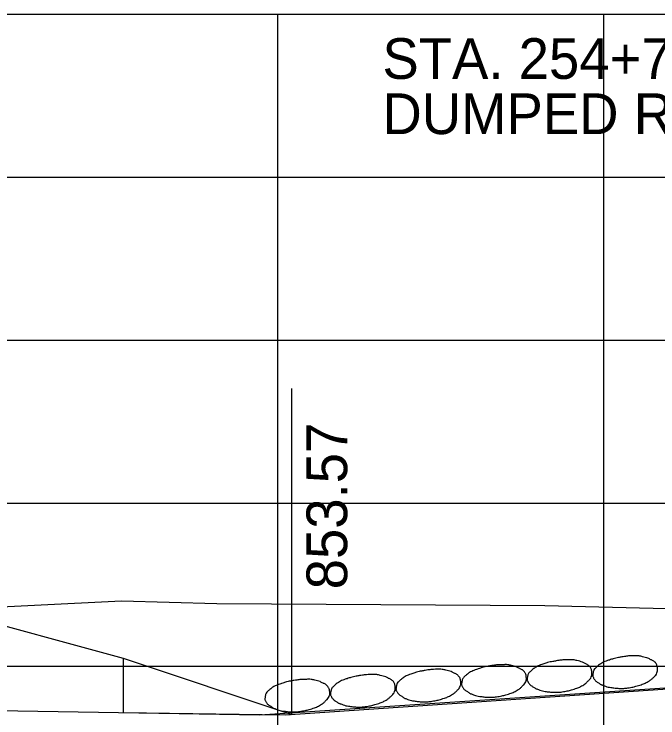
# Model space of a CAD drawing. Extents: x 1486524 to 1499135, y 326561 to 337924.
# Drawn here: x 1489014.79 to 1489034.55, y 328437.6 to 328459.19 of the extents above; entities that cross this region are included whole.
import ezdxf

# ---------------------------------------------------------------- set-up
doc = ezdxf.new("R2010")
doc.units = 0
for name, color, linetype in [('E_Ownership Information', 7, 'Continuous'), ('E_Proposed ROW Fig Annot', 7, 'Continuous'), ('E_Station Offset', 7, 'Continuous'), ('R_Xsect Elev', 7, 'Continuous'), ('T_Notes', 7, 'Continuous')]:
    doc.layers.add(name, color=color, linetype=linetype)

msp = doc.modelspace()

# ---------------------------------------------------------------- linework, layer by layer
at = {"layer": 'E_Ownership Information'}
for p, q in [((1488842.885, 328459.191), (1489122.885, 328459.191)), ((1489022.885, 328429.191), (1489022.885, 328459.191)), ((1489032.885, 328429.191), (1489032.885, 328459.191)), ((1488842.885, 328454.191), (1489122.885, 328454.191)), ((1488842.885, 328449.191), (1489122.885, 328449.191)), ((1488842.885, 328444.191), (1489122.885, 328444.191)), ((1488842.885, 328439.191), (1489122.885, 328439.191))]:
    msp.add_line(p, q, dxfattribs=at)
at = {"layer": 'E_Proposed ROW Fig Annot'}
for p, q in [((1489018.133, 328439.435), (1489018.133, 328437.765)), ((1488941.814, 328438.994), (1489022.333, 328437.698))]:
    msp.add_line(p, q, dxfattribs=at)
for points in [[(1489030.589, 328438.986), (1489030.572, 328438.968), (1489030.559, 328438.942), (1489030.549, 328438.896), (1489030.545, 328438.876), (1489030.537, 328438.828), (1489030.532, 328438.801), (1489030.531, 328438.759), (1489030.541, 328438.744), (1489030.561, 328438.702), (1489030.574, 328438.678), (1489030.607, 328438.634), (1489030.624, 328438.615), (1489030.675, 328438.579), (1489030.706, 328438.562), (1489030.755, 328438.529), (1489030.773, 328438.512), (1489030.809, 328438.492), (1489030.828, 328438.493), (1489030.88, 328438.474), (1489030.913, 328438.454), (1489031.011, 328438.426), (1489031.072, 328438.416), (1489031.226, 328438.396), (1489031.317, 328438.386), (1489031.5, 328438.387), (1489031.592, 328438.398), (1489031.781, 328438.431), (1489031.876, 328438.456), (1489032.071, 328438.516), (1489032.164, 328438.556), (1489032.314, 328438.645), (1489032.361, 328438.691), (1489032.449, 328438.779), (1489032.485, 328438.817), (1489032.519, 328438.905), (1489032.52, 328438.939), (1489032.519, 328439.004), (1489032.517, 328439.034), (1489032.503, 328439.096), (1489032.491, 328439.127), (1489032.459, 328439.173), (1489032.446, 328439.187), (1489032.412, 328439.216), (1489032.394, 328439.232), (1489032.347, 328439.255), (1489032.321, 328439.265), (1489032.266, 328439.292), (1489032.239, 328439.315), (1489032.139, 328439.34), (1489032.071, 328439.357), (1489031.942, 328439.39), (1489031.878, 328439.387), (1489031.729, 328439.385), (1489031.642, 328439.384), (1489031.496, 328439.364), (1489031.434, 328439.353), (1489031.31, 328439.331), (1489031.246, 328439.323), (1489031.15, 328439.295), (1489031.118, 328439.282), (1489031.04, 328439.256), (1489030.995, 328439.242), (1489030.898, 328439.21), (1489030.849, 328439.185), (1489030.771, 328439.141), (1489030.743, 328439.123), (1489030.681, 328439.073), (1489030.649, 328439.043), (1489030.6, 328438.998), (1489030.584, 328438.985), (1489030.573, 328438.966)], [(1489032.602, 328439.106), (1489032.585, 328439.088), (1489032.573, 328439.062), (1489032.562, 328439.016), (1489032.558, 328438.996), (1489032.55, 328438.948), (1489032.545, 328438.922), (1489032.545, 328438.879), (1489032.554, 328438.864), (1489032.574, 328438.822), (1489032.587, 328438.798), (1489032.621, 328438.754), (1489032.638, 328438.735), (1489032.688, 328438.699), (1489032.719, 328438.682), (1489032.769, 328438.649), (1489032.786, 328438.632), (1489032.822, 328438.612), (1489032.841, 328438.613), (1489032.893, 328438.594), (1489032.927, 328438.574), (1489033.024, 328438.546), (1489033.086, 328438.536), (1489033.239, 328438.516), (1489033.33, 328438.507), (1489033.514, 328438.507), (1489033.606, 328438.519), (1489033.794, 328438.551), (1489033.889, 328438.576), (1489034.084, 328438.636), (1489034.177, 328438.676), (1489034.327, 328438.765), (1489034.374, 328438.811), (1489034.462, 328438.9), (1489034.498, 328438.937), (1489034.533, 328439.025), (1489034.533, 328439.059), (1489034.532, 328439.124), (1489034.531, 328439.155), (1489034.516, 328439.216), (1489034.504, 328439.247), (1489034.473, 328439.294), (1489034.459, 328439.307), (1489034.425, 328439.336), (1489034.407, 328439.352), (1489034.36, 328439.375), (1489034.334, 328439.385), (1489034.279, 328439.412), (1489034.253, 328439.435), (1489034.152, 328439.46), (1489034.084, 328439.478), (1489033.955, 328439.51), (1489033.891, 328439.507), (1489033.742, 328439.505), (1489033.655, 328439.505), (1489033.509, 328439.484), (1489033.448, 328439.473), (1489033.323, 328439.451), (1489033.259, 328439.443), (1489033.163, 328439.415), (1489033.131, 328439.402), (1489033.053, 328439.376), (1489033.008, 328439.362), (1489032.912, 328439.33), (1489032.862, 328439.305), (1489032.784, 328439.262), (1489032.756, 328439.243), (1489032.694, 328439.194), (1489032.662, 328439.163), (1489032.614, 328439.119), (1489032.598, 328439.105), (1489032.586, 328439.086)], [(1489028.578, 328438.835), (1489028.561, 328438.817), (1489028.548, 328438.79), (1489028.538, 328438.744), (1489028.534, 328438.724), (1489028.526, 328438.677), (1489028.52, 328438.65), (1489028.52, 328438.608), (1489028.529, 328438.593), (1489028.55, 328438.551), (1489028.563, 328438.527), (1489028.596, 328438.482), (1489028.613, 328438.463), (1489028.664, 328438.428), (1489028.695, 328438.411), (1489028.744, 328438.378), (1489028.762, 328438.36), (1489028.798, 328438.34), (1489028.816, 328438.341), (1489028.869, 328438.323), (1489028.902, 328438.303), (1489029, 328438.274), (1489029.061, 328438.264), (1489029.215, 328438.244), (1489029.306, 328438.235), (1489029.489, 328438.235), (1489029.581, 328438.247), (1489029.769, 328438.28), (1489029.865, 328438.304), (1489030.059, 328438.365), (1489030.153, 328438.405), (1489030.303, 328438.494), (1489030.35, 328438.539), (1489030.438, 328438.628), (1489030.473, 328438.666), (1489030.508, 328438.753), (1489030.509, 328438.788), (1489030.508, 328438.853), (1489030.506, 328438.883), (1489030.492, 328438.945), (1489030.48, 328438.976), (1489030.448, 328439.022), (1489030.435, 328439.036), (1489030.401, 328439.065), (1489030.382, 328439.08), (1489030.336, 328439.104), (1489030.31, 328439.114), (1489030.255, 328439.14), (1489030.228, 328439.163), (1489030.128, 328439.189), (1489030.06, 328439.206), (1489029.931, 328439.239), (1489029.867, 328439.235), (1489029.718, 328439.234), (1489029.631, 328439.233), (1489029.484, 328439.212), (1489029.423, 328439.201), (1489029.299, 328439.179), (1489029.235, 328439.171), (1489029.139, 328439.144), (1489029.107, 328439.13), (1489029.029, 328439.105), (1489028.984, 328439.091), (1489028.887, 328439.058), (1489028.838, 328439.033), (1489028.76, 328438.99), (1489028.731, 328438.971), (1489028.67, 328438.922), (1489028.638, 328438.892), (1489028.589, 328438.847), (1489028.573, 328438.834), (1489028.561, 328438.815)], [(1489024.555, 328438.534), (1489024.538, 328438.516), (1489024.526, 328438.49), (1489024.515, 328438.443), (1489024.512, 328438.423), (1489024.504, 328438.376), (1489024.498, 328438.349), (1489024.498, 328438.307), (1489024.507, 328438.292), (1489024.528, 328438.25), (1489024.541, 328438.226), (1489024.574, 328438.182), (1489024.591, 328438.162), (1489024.641, 328438.127), (1489024.673, 328438.11), (1489024.722, 328438.077), (1489024.739, 328438.06), (1489024.776, 328438.039), (1489024.794, 328438.04), (1489024.846, 328438.022), (1489024.88, 328438.002), (1489024.977, 328437.974), (1489025.039, 328437.964), (1489025.193, 328437.943), (1489025.283, 328437.934), (1489025.467, 328437.935), (1489025.559, 328437.946), (1489025.747, 328437.979), (1489025.843, 328438.003), (1489026.037, 328438.064), (1489026.13, 328438.104), (1489026.28, 328438.193), (1489026.328, 328438.238), (1489026.416, 328438.327), (1489026.451, 328438.365), (1489026.486, 328438.453), (1489026.486, 328438.487), (1489026.486, 328438.552), (1489026.484, 328438.582), (1489026.469, 328438.644), (1489026.457, 328438.675), (1489026.426, 328438.721), (1489026.413, 328438.735), (1489026.378, 328438.764), (1489026.36, 328438.78), (1489026.314, 328438.803), (1489026.288, 328438.813), (1489026.233, 328438.84), (1489026.206, 328438.862), (1489026.106, 328438.888), (1489026.038, 328438.905), (1489025.909, 328438.938), (1489025.844, 328438.935), (1489025.695, 328438.933), (1489025.609, 328438.932), (1489025.462, 328438.911), (1489025.401, 328438.901), (1489025.276, 328438.878), (1489025.212, 328438.87), (1489025.117, 328438.843), (1489025.084, 328438.83), (1489025.007, 328438.804), (1489024.962, 328438.79), (1489024.865, 328438.757), (1489024.816, 328438.733), (1489024.737, 328438.689), (1489024.709, 328438.67), (1489024.647, 328438.621), (1489024.615, 328438.591), (1489024.567, 328438.546), (1489024.551, 328438.533), (1489024.539, 328438.514)], [(1489026.566, 328438.694), (1489026.549, 328438.676), (1489026.536, 328438.649), (1489026.526, 328438.603), (1489026.522, 328438.583), (1489026.514, 328438.536), (1489026.508, 328438.509), (1489026.508, 328438.467), (1489026.517, 328438.452), (1489026.538, 328438.41), (1489026.551, 328438.386), (1489026.584, 328438.341), (1489026.601, 328438.322), (1489026.652, 328438.287), (1489026.683, 328438.27), (1489026.732, 328438.237), (1489026.75, 328438.22), (1489026.786, 328438.199), (1489026.805, 328438.2), (1489026.857, 328438.182), (1489026.89, 328438.162), (1489026.988, 328438.133), (1489027.049, 328438.123), (1489027.203, 328438.103), (1489027.294, 328438.094), (1489027.477, 328438.094), (1489027.569, 328438.106), (1489027.758, 328438.139), (1489027.853, 328438.163), (1489028.048, 328438.224), (1489028.141, 328438.264), (1489028.291, 328438.353), (1489028.338, 328438.398), (1489028.426, 328438.487), (1489028.462, 328438.525), (1489028.496, 328438.612), (1489028.497, 328438.647), (1489028.496, 328438.712), (1489028.494, 328438.742), (1489028.48, 328438.804), (1489028.468, 328438.835), (1489028.436, 328438.881), (1489028.423, 328438.895), (1489028.389, 328438.924), (1489028.371, 328438.94), (1489028.324, 328438.963), (1489028.298, 328438.973), (1489028.243, 328438.999), (1489028.216, 328439.022), (1489028.116, 328439.048), (1489028.048, 328439.065), (1489027.919, 328439.098), (1489027.855, 328439.094), (1489027.706, 328439.093), (1489027.619, 328439.092), (1489027.473, 328439.071), (1489027.411, 328439.06), (1489027.287, 328439.038), (1489027.223, 328439.03), (1489027.127, 328439.003), (1489027.095, 328438.989), (1489027.017, 328438.964), (1489026.972, 328438.95), (1489026.875, 328438.917), (1489026.826, 328438.893), (1489026.748, 328438.849), (1489026.72, 328438.83), (1489026.658, 328438.781), (1489026.626, 328438.751), (1489026.577, 328438.706), (1489026.561, 328438.693), (1489026.55, 328438.674)], [(1489022.544, 328438.386), (1489022.527, 328438.368), (1489022.514, 328438.342), (1489022.504, 328438.295), (1489022.5, 328438.275), (1489022.492, 328438.228), (1489022.487, 328438.201), (1489022.486, 328438.159), (1489022.496, 328438.144), (1489022.516, 328438.102), (1489022.529, 328438.078), (1489022.562, 328438.034), (1489022.579, 328438.014), (1489022.63, 328437.979), (1489022.661, 328437.962), (1489022.711, 328437.929), (1489022.728, 328437.912), (1489022.764, 328437.891), (1489022.783, 328437.892), (1489022.835, 328437.874), (1489022.868, 328437.854), (1489022.966, 328437.825), (1489023.028, 328437.815), (1489023.181, 328437.795), (1489023.272, 328437.786), (1489023.456, 328437.787), (1489023.548, 328437.798), (1489023.736, 328437.831), (1489023.831, 328437.855), (1489024.026, 328437.916), (1489024.119, 328437.956), (1489024.269, 328438.045), (1489024.316, 328438.09), (1489024.404, 328438.179), (1489024.44, 328438.217), (1489024.475, 328438.304), (1489024.475, 328438.339), (1489024.474, 328438.404), (1489024.472, 328438.434), (1489024.458, 328438.496), (1489024.446, 328438.527), (1489024.414, 328438.573), (1489024.401, 328438.587), (1489024.367, 328438.616), (1489024.349, 328438.632), (1489024.302, 328438.655), (1489024.276, 328438.665), (1489024.221, 328438.692), (1489024.195, 328438.714), (1489024.094, 328438.74), (1489024.026, 328438.757), (1489023.897, 328438.79), (1489023.833, 328438.786), (1489023.684, 328438.785), (1489023.597, 328438.784), (1489023.451, 328438.763), (1489023.39, 328438.753), (1489023.265, 328438.73), (1489023.201, 328438.722), (1489023.105, 328438.695), (1489023.073, 328438.682), (1489022.995, 328438.656), (1489022.95, 328438.642), (1489022.853, 328438.609), (1489022.804, 328438.585), (1489022.726, 328438.541), (1489022.698, 328438.522), (1489022.636, 328438.473), (1489022.604, 328438.443), (1489022.556, 328438.398), (1489022.54, 328438.385), (1489022.528, 328438.366)]]:
    msp.add_open_spline(points, degree=3, dxfattribs=at)
at = {"layer": 'E_Station Offset'}
msp.add_line((1489018.133, 328439.435), (1489023.308, 328437.711), dxfattribs=at)
at = {"layer": 'R_Xsect Elev'}
msp.add_line((1489023.308, 328437.711), (1489023.308, 328447.711), dxfattribs=at)
at = {"layer": 'T_Notes'}
for p, q in [((1489022.333, 328437.698), (1489062.966, 328440.404)), ((1488945.123, 328438.941), (1489022.333, 328437.698))]:
    msp.add_line(p, q, dxfattribs=at)
for points in [[(1488924.201, 328444.819), (1488941.814, 328438.994), (1488945.123, 328438.941), (1488948.403, 328438.888), (1488948.403, 328440.558), (1488953.653, 328441.804), (1488965.953, 328443.793), (1488965.991, 328443.803), (1488969.607, 328443.947), (1488969.653, 328443.949), (1488982.72, 328444.21), (1488982.885, 328444.214), (1488994.732, 328444.128), (1488994.885, 328444.126), (1488994.936, 328444.124), (1488998.989, 328443.962), (1488999.026, 328443.953), (1489012.883, 328440.868), (1489018.133, 328439.435), (1489018.133, 328437.765), (1489023.119, 328437.698), (1489062.966, 328440.404)], [(1489012.538, 328440.92), (1489018.082, 328441.198), (1489021.013, 328441.107), (1489031.072, 328441.046), (1489052.675, 328440.521), (1489056.279, 328440.356)]]:
    msp.add_lwpolyline(points, dxfattribs=at)

# ---------------------------------------------------------------- texts
at = {"layer": 'E_Proposed ROW Fig Annot'}
for s, p in [('STA. 254+73 INSTALL', (1489026.093, 328457.202)), ('DUMPED RIPRAP ON RT. 12 CU.YD.', (1489026.093, 328455.509))]:
    msp.add_text(s, height=1.25, dxfattribs=at).set_placement(p)
at = {"layer": 'T_Notes'}
msp.add_text('853.57', height=1.25, rotation=90, dxfattribs=at).set_placement((1489025.012, 328441.546))

doc.saveas('drawing.dxf')
